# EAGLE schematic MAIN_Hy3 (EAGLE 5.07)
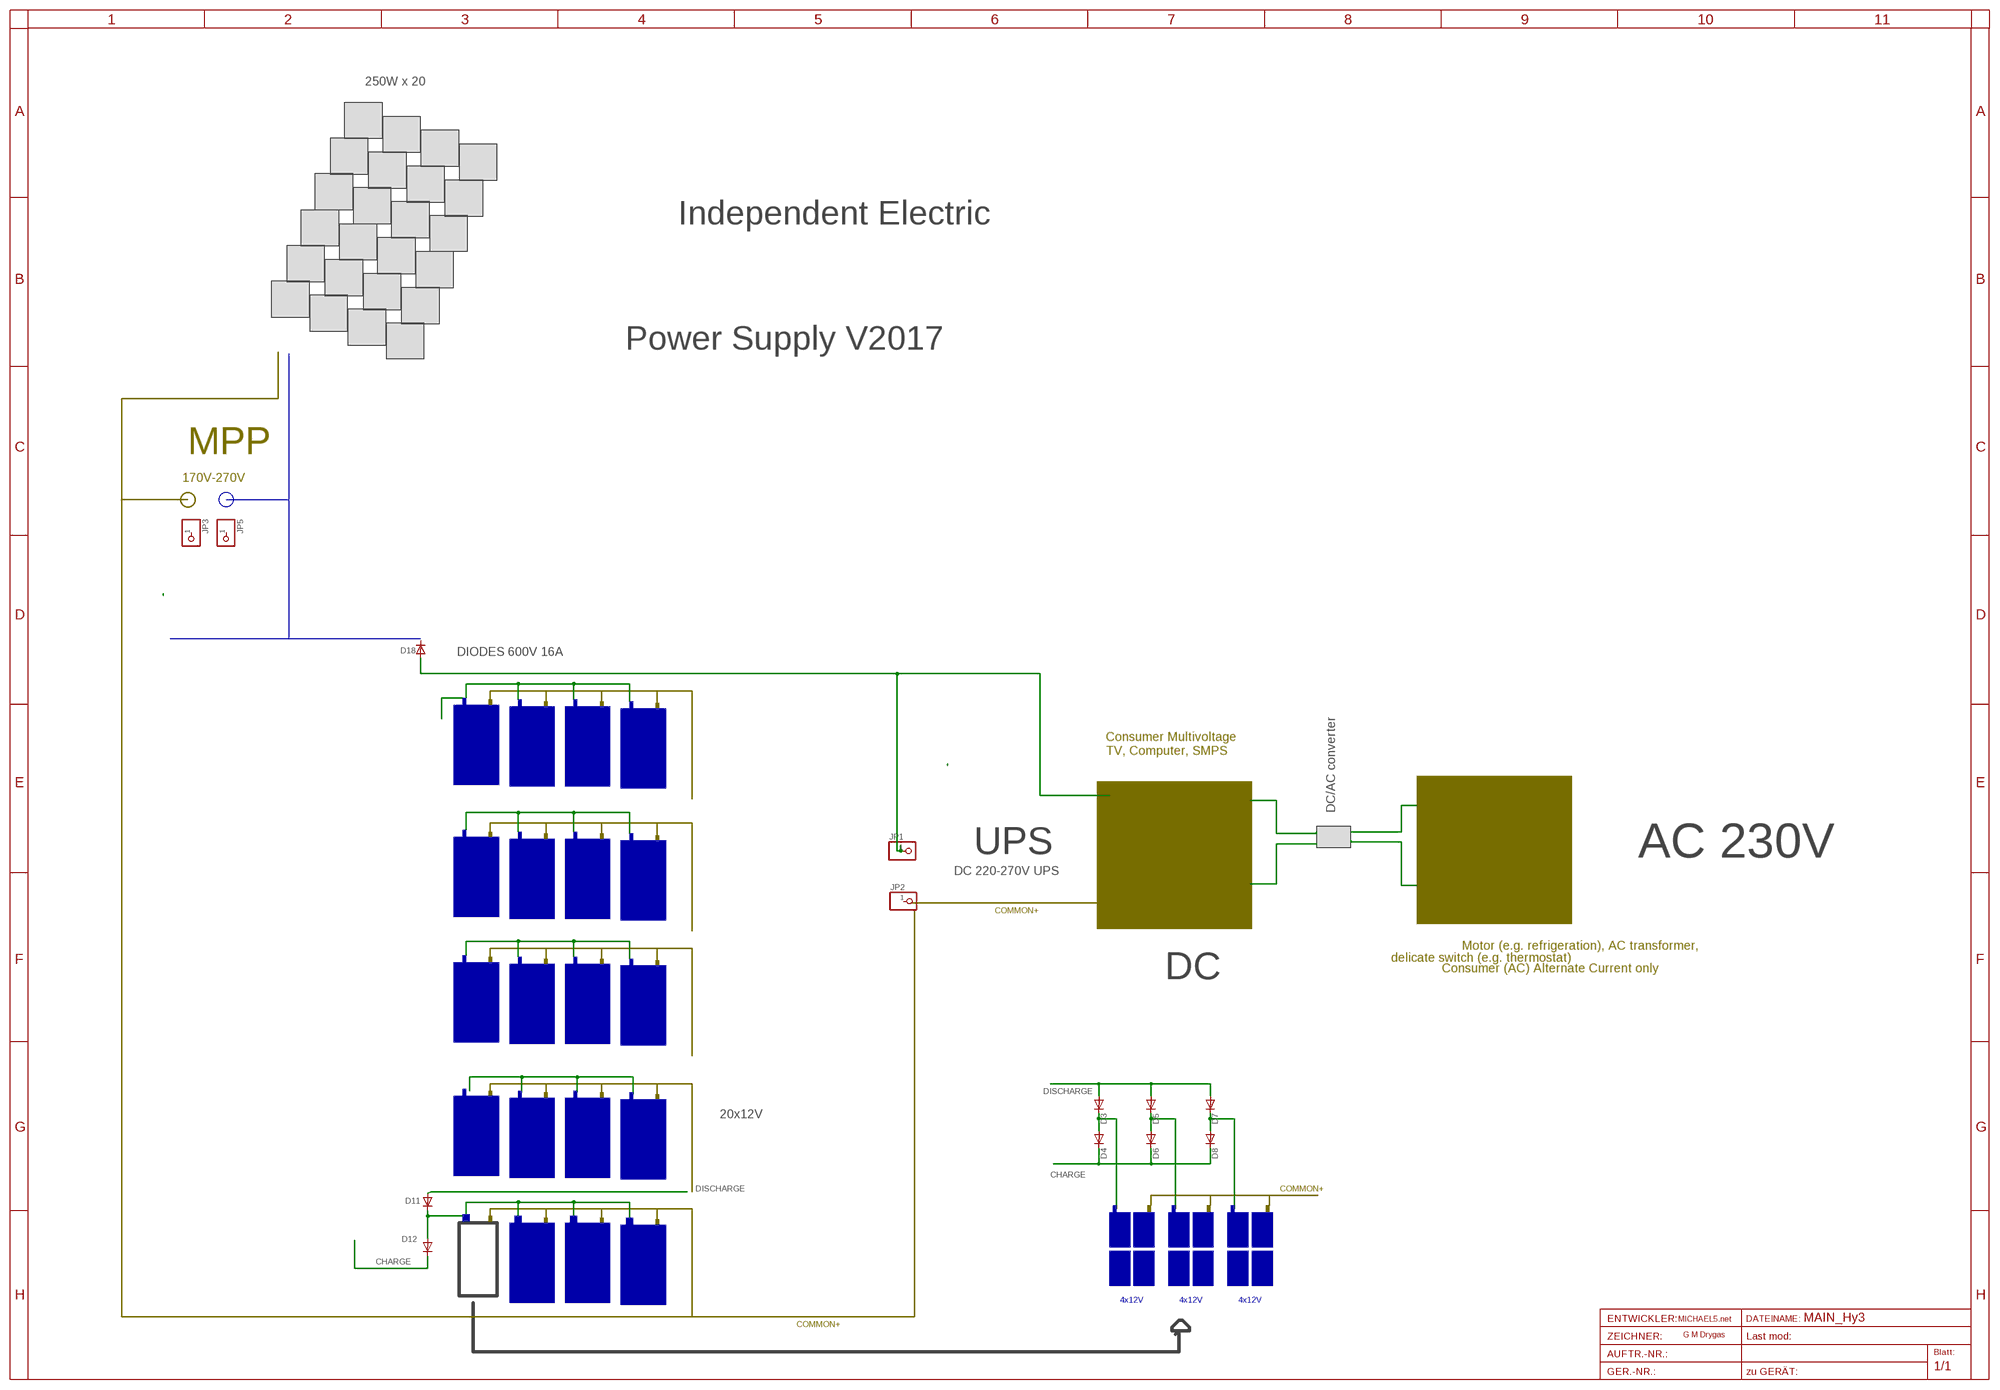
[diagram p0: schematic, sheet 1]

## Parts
D3  DIODE-SMC  [SMC]
D4  DIODE-SMC  [SMC]
D5  DIODE-SMC  [SMC]
D6  DIODE-SMC  [SMC]
D7  DIODE-SMC  [SMC]
D8  DIODE-SMC  [SMC]
D11  DIODE-SMC  [SMC]
D12  DIODE-SMC  [SMC]
D18  DIODE-SMC  [SMC]
JP1  PINHD-1X14.5MM  [1X4MM5]
JP2  PINHD-1X14.5MM  [1X4MM5]
JP3  PINHD-1X14.5MM  [1X4MM5]
JP5  PINHD-1X14.5MM  [1X4MM5]

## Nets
CHARGE: D4.C D6.C D8.C D12.C
DISCHARGE: D3.A D5.A D7.A D11.A
N$12: D11.C D12.A
N$17: D18.A JP1.1
N$24: D3.C D4.A
N$27: D5.C D6.A
N$30: D7.C D8.A
Unconnected: D18.C JP2.1 JP3.1 JP5.1

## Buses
B$1
B$2

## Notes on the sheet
- 250W x 20
- Independent Electric
- Power Supply V2017
- MPP
- 170V-270V
- DIODES 600V 16A
- Consumer Multivoltage
- TV, Computer, SMPS
- DC/AC converter
- UPS | AC 230V
- DC 220-270V UPS
- COMMON+
- Motor (e.g. refrigeration), AC transformer,
- delicate switch (e.g. thermostat) | Consumer (AC) Alternate Current only
- DC
- 20x12V
- COMMON+
- 4x12V | 4x12V | 4x12V
- MICHAEL5.net
- COMMON+
- G M Drygas

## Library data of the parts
D3-D8 D11 D12 D18 = diode:DIODE-: DIODE
JP1-JP3 JP5 = pinhead:PINHD-1X1: PIN HEADER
